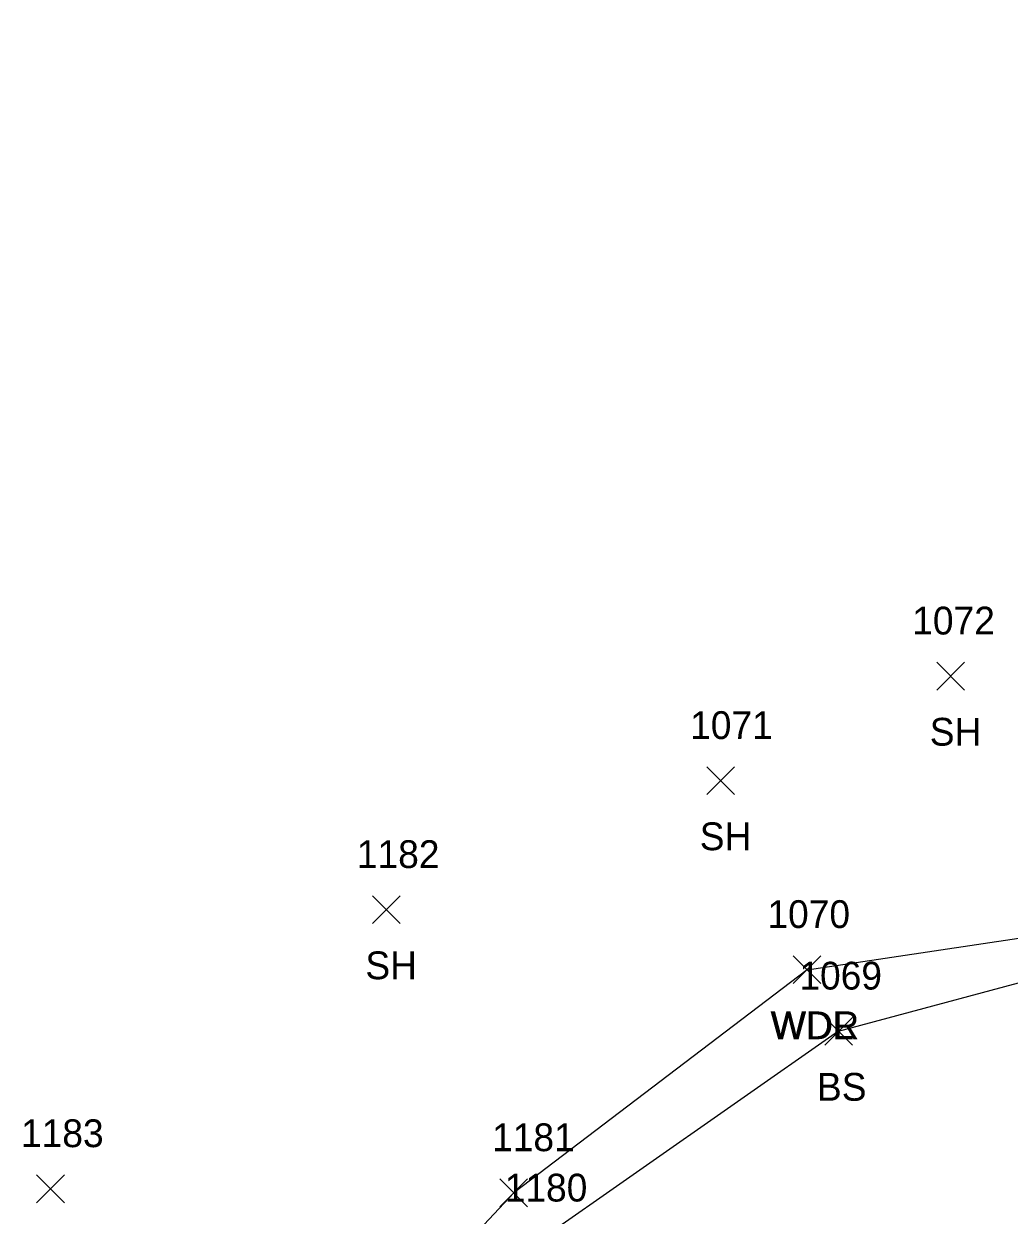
# Model space of a CAD drawing. Extents: x 1879695 to 1880991, y 836466 to 845172.
# Drawn here: x 1879695 to 1879765.9, y 844375.9 to 844461.6 of the extents above; entities that cross this region are included whole.
import ezdxf

# ---------------------------------------------------------------- set-up
doc = ezdxf.new("R2010")
doc.units = 0
for name, color, linetype in [('L_A', 7, 'Continuous'), ('L_I', 7, 'Continuous'), ('L_TIC', 7, 'Continuous'), ('LAWA', 7, 'Continuous'), ('LELB', 7, 'Continuous')]:
    doc.layers.add(name, color=color, linetype=linetype)

msp = doc.modelspace()

# ---------------------------------------------------------------- linework, layer by layer
at = {"layer": 'L_TIC'}
for points in [[(1879760.705, 844413.672), (1879762.705, 844415.672)], [(1879762.705, 844413.672), (1879760.705, 844415.672)], [(1879744.15, 844406.15), (1879746.15, 844408.15)], [(1879746.15, 844406.15), (1879744.15, 844408.15)], [(1879720.083, 844396.866), (1879722.083, 844398.866)], [(1879722.083, 844396.866), (1879720.083, 844398.866)], [(1879750.367, 844392.55), (1879752.367, 844394.55)], [(1879752.367, 844392.55), (1879750.367, 844394.55)], [(1879750.367, 844392.55), (1879752.367, 844394.55)], [(1879752.367, 844392.55), (1879750.367, 844394.55)], [(1879752.636, 844388.122), (1879754.636, 844390.122)], [(1879754.636, 844388.122), (1879752.636, 844390.122)], [(1879752.636, 844388.122), (1879754.636, 844390.122)], [(1879754.636, 844388.122), (1879752.636, 844390.122)], [(1879695.908, 844376.782), (1879697.908, 844378.782)], [(1879697.908, 844376.782), (1879695.908, 844378.782)], [(1879729.249, 844376.493), (1879731.249, 844378.493)], [(1879731.249, 844376.493), (1879729.249, 844378.493)], [(1879729.249, 844376.493), (1879731.249, 844378.493)], [(1879731.249, 844376.493), (1879729.249, 844378.493)]]:
    msp.add_lwpolyline(points, dxfattribs=at)
at = {"layer": 'LAWA'}
for points in [[(1879751.367, 844393.55), (1879769.647, 844396.265), (1879790.458, 844419.82), (1879805.93, 844425.565), (1879817.218, 844439.81), (1879827.458, 844449.754), (1879840.76, 844461.612)], [(1879751.367, 844393.55), (1879730.249, 844377.493)], [(1879722.008, 844368.703), (1879730.249, 844377.493)]]:
    msp.add_lwpolyline(points, dxfattribs=at)
at = {"layer": 'LELB'}
for points in [[(1879753.636, 844389.122), (1879770.794, 844393.728), (1879792.057, 844415.134), (1879806.804, 844422.782), (1879819.962, 844435.134), (1879827.458, 844449.754)], [(1879753.636, 844389.122), (1879731.813, 844373.87)]]:
    msp.add_lwpolyline(points, dxfattribs=at)

# ---------------------------------------------------------------- texts
at = {"layer": 'L_A'}
for s, p in [('SH', (1879760.194, 844409.672)), ('SH', (1879743.639, 844402.15)), ('SH', (1879719.571, 844392.866)), ('WDR', (1879748.729, 844388.55)), ('WDL', (1879748.785, 844388.55)), ('BS', (1879752.077, 844384.122)), ('BS', (1879752.077, 844384.122))]:
    msp.add_text(s, height=2, dxfattribs=at).set_placement(p)
at = {"layer": 'L_I'}
for s, p in [('1072', (1879758.934, 844417.672)), ('1071', (1879742.946, 844410.15)), ('1182', (1879718.957, 844400.866)), ('1070', (1879748.509, 844396.55)), ('1070', (1879748.509, 844396.55)), ('1069', (1879750.809, 844392.122)), ('1069', (1879750.809, 844392.122)), ('1183', (1879694.782, 844380.782)), ('1181', (1879728.69, 844380.493)), ('1181', (1879728.69, 844380.493)), ('1180', (1879729.6, 844376.87)), ('1180', (1879729.6, 844376.87))]:
    msp.add_text(s, height=2, dxfattribs=at).set_placement(p)

doc.saveas('drawing.dxf')
